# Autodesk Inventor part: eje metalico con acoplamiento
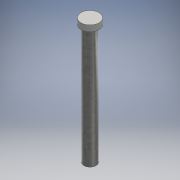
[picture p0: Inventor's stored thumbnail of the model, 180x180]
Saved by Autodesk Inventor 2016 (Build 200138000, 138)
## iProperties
Created: 2016-06
Part Number: eje metalico con acoplamiento
Material: Genérico
Document SubType Name: Modeling
Designer: adm
Density: 1 g/cm^3
Appearance: Valor por defecto
Author: adm
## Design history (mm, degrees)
sketch "Boceto1"
  geometry: C1 r 5 at (0, 0); 1 further point
  constraints: 1 centre point, 1 coincident
  dimensions: "d0" = 10 diameter of C1
extrude "Extrusión1" new body sketch "Boceto1" distance "d1" = 100; taper "d2" = 0 deg
sketch "Boceto2"
  geometry: C1 r 7.5 at (0, 0); 1 further point
  constraints: 1 centre point, 1 coincident
  dimensions: "d3" = 15 diameter of C1
extrude "Extrusión2" join sketch "Boceto2" distance "d4" = 5; taper "d5" = 0 deg
node "Sólido1"
